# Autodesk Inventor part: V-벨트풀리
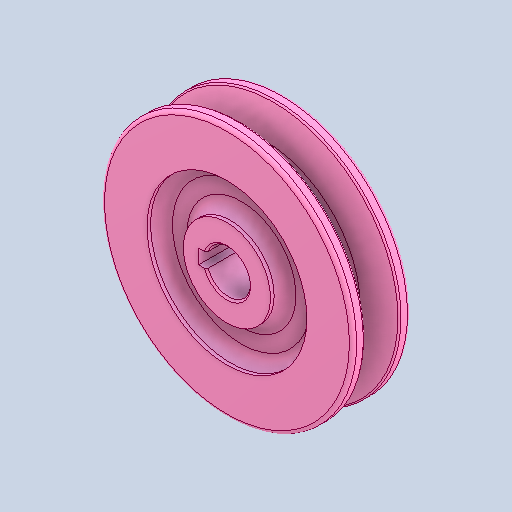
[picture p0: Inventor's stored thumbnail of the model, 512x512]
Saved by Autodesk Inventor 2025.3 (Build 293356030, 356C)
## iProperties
Created: 2025-08
Part Number: V-벨트풀리
Material: 강철, 연강
Document SubType Name: Modeling
Designer: user
Density: 7.86 g/cm^3
Appearance: 기본값
Author: jhkim
Sending System: Autodesk Inventor 2026
Preprocessor: ST-DEVELOPER v20.1
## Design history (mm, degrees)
sketch "스케치1"
  geometry: 1 further point
  constraints: 1 other
feature "Solid1"
node "솔리드1"
